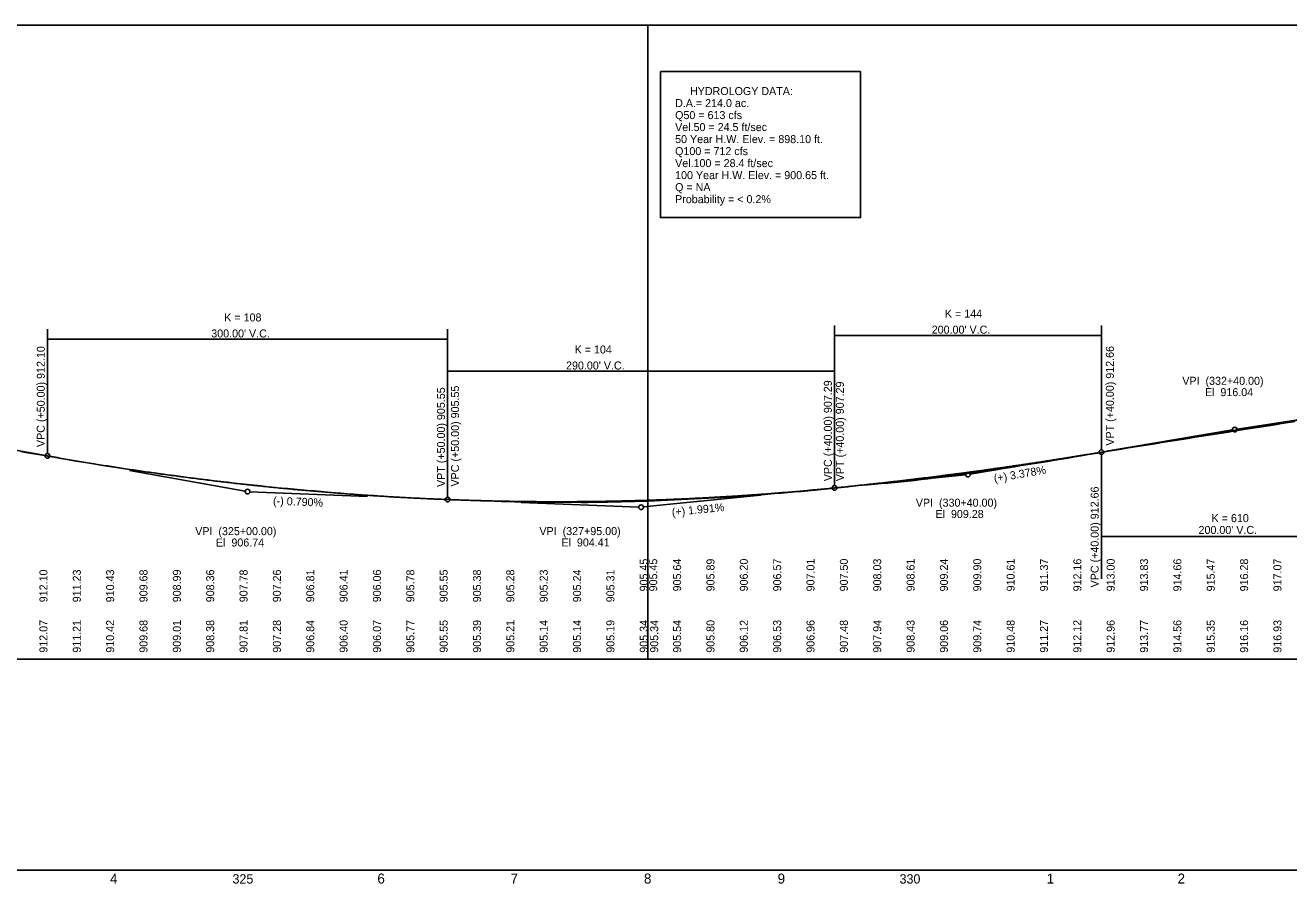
# Model space of a CAD drawing. Extents: x 4180 to 16997695, y 4 to 12629821.
# Drawn here: x 16984753 to 16985700, y 12626778 to 12627421 of the extents above; entities that cross this region are included whole.
import ezdxf

# ---------------------------------------------------------------- set-up
doc = ezdxf.new("R2010")
doc.units = 0
for name, color, linetype in [('Default', 7, 'Continuous'), ('RD_DDB_EX_Tx', 7, 'Continuous'), ('RD_DDB_GradeTX', 7, 'Continuous'), ('RD_DDB_PI', 7, 'Continuous'), ('RD_DDB_Profile_EX', 7, 'Continuous'), ('RD_DDB_Profile_PR', 7, 'Continuous'), ('RD_DDB_StaTX', 7, 'Continuous'), ('RD_DDB_StripGrade', 7, 'Continuous'), ('RD_DDB_StripGrade_PR', 7, 'Continuous'), ('RD_DDB_VCLbl', 7, 'Continuous'), ('RD_GPK_Profile_Cell', 7, 'Continuous')]:
    doc.layers.add(name, color=color, linetype=linetype)

msp = doc.modelspace()

# ---------------------------------------------------------------- linework, layer by layer
at = {"layer": 'Default'}
for points in [[(16983719.88, 12626945.95), (16985219.88, 12626945.95), (16985219.88, 12627420.95), (16983719.88, 12627420.95)], [(16985219.88, 12626945.95), (16986719.88, 12626945.95), (16986719.88, 12627420.95), (16985219.88, 12627420.95)]]:
    msp.add_lwpolyline(points, close=True, dxfattribs=at)
at = {"layer": 'RD_DDB_EX_Tx'}
msp.add_lwpolyline([(16985229.36, 12627386.27), (16985379.36, 12627386.27), (16985379.36, 12627276.8), (16985229.36, 12627276.8)], close=True, dxfattribs=at)
at = {"layer": 'RD_DDB_PI'}
for p, q in [((16985748.85, 12627131.56), (16985661.6, 12627118.25)), ((16985571.13, 12627103), (16985658.15, 12627117.7)), ((16985548.62, 12627099.2), (16985461.6, 12627084.5)), ((16984831.28, 12627087.3), (16984918.15, 12627071.78)), ((16985370.32, 12627075.3), (16985458.13, 12627084.04)), ((16985009.8, 12627067.92), (16984921.62, 12627071.41)), ((16985304.43, 12627068.74), (16985216.62, 12627060)), ((16985124.95, 12627063.38), (16985213.13, 12627059.89))]:
    msp.add_line(p, q, dxfattribs=at)
for centre in [(16985659.88, 12627117.99), (16985459.88, 12627084.21), (16984919.88, 12627071.48), (16985214.88, 12627059.82)]:
    msp.add_circle(centre, 1.75, dxfattribs=at)
at = {"layer": 'RD_DDB_Profile_EX'}
for points in [[(16985619.88, 12627110.57), (16985624.88, 12627111.37), (16985629.88, 12627112.18), (16985634.88, 12627112.98), (16985639.88, 12627113.75), (16985644.88, 12627114.52), (16985649.88, 12627115.3), (16985654.88, 12627116.15), (16985659.88, 12627116.99), (16985664.88, 12627117.83), (16985669.88, 12627118.61), (16985674.88, 12627119.33), (16985679.88, 12627120.05), (16985684.88, 12627120.81), (16985689.88, 12627121.62), (16985694.88, 12627122.43), (16985699.88, 12627123.24), (16985704.88, 12627124.04)], [(16984749.88, 12627101.54), (16984754.88, 12627100.66), (16984759.88, 12627099.81), (16984764.88, 12627098.96), (16984769.88, 12627098.12), (16984774.88, 12627097.24), (16984779.88, 12627096.35), (16984784.88, 12627095.47), (16984789.88, 12627094.63), (16984794.88, 12627093.85), (16984799.88, 12627093.05), (16984804.88, 12627092.24), (16984809.88, 12627091.44), (16984814.88, 12627090.64), (16984819.88, 12627089.89), (16984824.88, 12627089.14), (16984829.88, 12627088.4), (16984834.88, 12627087.66), (16984839.88, 12627086.93), (16984844.88, 12627086.2), (16984849.88, 12627085.48), (16984854.88, 12627084.79), (16984859.88, 12627084.14), (16984864.88, 12627083.49), (16984869.88, 12627082.84), (16984874.88, 12627082.19), (16984879.88, 12627081.54), (16984884.88, 12627080.89), (16984889.88, 12627080.25), (16984894.88, 12627079.67), (16984899.88, 12627079.08), (16984904.88, 12627078.49), (16984909.88, 12627077.91), (16984914.88, 12627077.36), (16984919.88, 12627076.82), (16984924.88, 12627076.28), (16984929.88, 12627075.74), (16984934.88, 12627075.2), (16984939.88, 12627074.65), (16984944.88, 12627074.18), (16984949.88, 12627073.76), (16984954.88, 12627073.33), (16984959.88, 12627072.91), (16984964.88, 12627072.45), (16984969.88, 12627072), (16984974.88, 12627071.55), (16984979.88, 12627071.04), (16984984.88, 12627070.63), (16984989.88, 12627070.22), (16984994.88, 12627069.81), (16984999.88, 12627069.45), (16985004.88, 12627069.13), (16985009.88, 12627068.8), (16985014.88, 12627068.48), (16985019.88, 12627068.12), (16985024.88, 12627067.76), (16985029.88, 12627067.44), (16985034.88, 12627067.16), (16985039.88, 12627066.9), (16985044.88, 12627066.65), (16985049.88, 12627066.41), (16985054.88, 12627066.16), (16985059.88, 12627065.92), (16985064.88, 12627065.74), (16985069.88, 12627065.56), (16985074.88, 12627065.38), (16985079.88, 12627065.2), (16985084.88, 12627065.05), (16985089.88, 12627064.9), (16985094.88, 12627064.74), (16985099.88, 12627064.55), (16985104.88, 12627064.36), (16985109.88, 12627064.19), (16985114.88, 12627064.03), (16985119.88, 12627063.86)], [(16985119.88, 12627063.86), (16985124.88, 12627063.71), (16985129.88, 12627063.65), (16985134.88, 12627063.59), (16985139.88, 12627063.54), (16985144.88, 12627063.48), (16985149.88, 12627063.47), (16985154.88, 12627063.49), (16985159.88, 12627063.5), (16985164.88, 12627063.53), (16985169.88, 12627063.47), (16985174.88, 12627063.45), (16985179.88, 12627063.52), (16985184.88, 12627063.58), (16985189.88, 12627063.65), (16985194.88, 12627063.75), (16985199.88, 12627063.88), (16985204.88, 12627064.01), (16985209.88, 12627064.14), (16985214.88, 12627064.29), (16985219.88, 12627064.47), (16985224.88, 12627064.64), (16985229.88, 12627064.82), (16985234.88, 12627065.04), (16985239.88, 12627065.27), (16985244.88, 12627065.51), (16985249.88, 12627065.75), (16985254.88, 12627065.99), (16985259.88, 12627066.25), (16985264.88, 12627066.51), (16985269.88, 12627066.77), (16985274.88, 12627067.04), (16985279.88, 12627067.37), (16985284.88, 12627067.7), (16985289.88, 12627068.04), (16985294.88, 12627068.38), (16985299.88, 12627068.79), (16985304.88, 12627069.21), (16985309.88, 12627069.63), (16985314.88, 12627070.04), (16985319.88, 12627070.46), (16985324.88, 12627070.87), (16985329.88, 12627071.29), (16985334.88, 12627071.71), (16985339.88, 12627072.13), (16985344.88, 12627072.57), (16985349.88, 12627073.08), (16985354.88, 12627073.59), (16985359.88, 12627074.11), (16985364.88, 12627074.65), (16985369.88, 12627075.19), (16985374.88, 12627075.73), (16985379.88, 12627076.26), (16985384.88, 12627076.67), (16985389.88, 12627077.08), (16985394.88, 12627077.48), (16985399.88, 12627077.94), (16985404.88, 12627078.38), (16985409.88, 12627078.83), (16985414.88, 12627079.35), (16985419.88, 12627079.95), (16985424.88, 12627080.55), (16985429.88, 12627081.17), (16985434.88, 12627081.8), (16985439.88, 12627082.44), (16985444.88, 12627083.09), (16985449.88, 12627083.75), (16985454.88, 12627084.42), (16985459.88, 12627085.08), (16985464.88, 12627085.77), (16985469.88, 12627086.47), (16985474.88, 12627087.17), (16985479.88, 12627087.88), (16985484.88, 12627088.6), (16985489.88, 12627089.38), (16985494.88, 12627090.16), (16985499.88, 12627090.95), (16985504.88, 12627091.75), (16985509.88, 12627092.55), (16985514.88, 12627093.34), (16985519.88, 12627094.16), (16985524.88, 12627095), (16985529.88, 12627095.84), (16985534.88, 12627096.68), (16985539.88, 12627097.53), (16985544.88, 12627098.38), (16985549.88, 12627099.24), (16985554.88, 12627100.08), (16985559.88, 12627100.93), (16985564.88, 12627101.77), (16985569.88, 12627102.58), (16985574.88, 12627103.39), (16985579.88, 12627104.2), (16985584.88, 12627105.01), (16985589.88, 12627105.82), (16985594.88, 12627106.62), (16985599.88, 12627107.41), (16985604.88, 12627108.2), (16985609.88, 12627108.98), (16985614.88, 12627109.77), (16985619.88, 12627110.57)]]:
    msp.add_lwpolyline(points, dxfattribs=at)
at = {"layer": 'RD_DDB_Profile_PR'}
msp.add_line((16984619.88, 12627125.07), (16984769.88, 12627098.27), dxfattribs=at)
for points in [[(16985559.88, 12627101.1), (16985563.88, 12627101.77), (16985567.88, 12627102.45), (16985571.88, 12627103.12), (16985575.88, 12627103.79), (16985579.88, 12627104.46), (16985583.88, 12627105.13), (16985587.88, 12627105.8), (16985591.88, 12627106.46), (16985595.88, 12627107.13), (16985599.88, 12627107.79), (16985603.88, 12627108.45), (16985607.88, 12627109.11), (16985611.88, 12627109.77), (16985615.88, 12627110.43), (16985619.88, 12627111.09), (16985623.88, 12627111.74), (16985627.88, 12627112.4), (16985631.88, 12627113.05), (16985635.88, 12627113.7), (16985639.88, 12627114.35), (16985643.88, 12627115), (16985647.88, 12627115.65), (16985651.88, 12627116.29), (16985655.88, 12627116.94), (16985659.88, 12627117.58), (16985663.88, 12627118.22), (16985667.88, 12627118.86), (16985671.88, 12627119.5), (16985675.88, 12627120.14), (16985679.88, 12627120.78), (16985683.88, 12627121.41), (16985687.88, 12627122.05), (16985691.88, 12627122.68), (16985695.88, 12627123.31), (16985699.88, 12627123.94), (16985703.88, 12627124.57), (16985707.88, 12627125.2), (16985711.88, 12627125.82), (16985715.88, 12627126.45), (16985719.88, 12627127.07), (16985723.88, 12627127.7), (16985727.88, 12627128.32), (16985731.88, 12627128.94), (16985735.88, 12627129.56), (16985739.88, 12627130.17), (16985743.88, 12627130.79), (16985747.88, 12627131.4), (16985751.88, 12627132.02), (16985755.88, 12627132.63), (16985759.88, 12627133.24)], [(16984769.88, 12627098.27), (16984775.88, 12627097.21), (16984781.88, 12627096.16), (16984787.88, 12627095.13), (16984793.88, 12627094.12), (16984799.88, 12627093.12), (16984805.88, 12627092.14), (16984811.88, 12627091.18), (16984817.88, 12627090.23), (16984823.88, 12627089.3), (16984829.88, 12627088.39), (16984835.88, 12627087.49), (16984841.88, 12627086.61), (16984847.88, 12627085.75), (16984853.88, 12627084.9), (16984859.88, 12627084.07), (16984865.88, 12627083.26), (16984871.88, 12627082.46), (16984877.88, 12627081.68), (16984883.88, 12627080.92), (16984889.88, 12627080.17), (16984895.88, 12627079.45), (16984901.88, 12627078.73), (16984907.88, 12627078.04), (16984913.88, 12627077.36), (16984919.88, 12627076.69), (16984925.88, 12627076.05), (16984931.88, 12627075.42), (16984937.88, 12627074.81), (16984943.88, 12627074.21), (16984949.88, 12627073.63), (16984955.88, 12627073.07), (16984961.88, 12627072.52), (16984967.88, 12627071.99), (16984973.88, 12627071.48), (16984979.88, 12627070.98), (16984985.88, 12627070.51), (16984991.88, 12627070.04), (16984997.88, 12627069.6), (16985003.88, 12627069.17), (16985009.88, 12627068.76), (16985015.88, 12627068.36), (16985021.88, 12627067.98), (16985027.88, 12627067.62), (16985033.88, 12627067.27), (16985039.88, 12627066.94), (16985045.88, 12627066.63), (16985051.88, 12627066.34), (16985057.88, 12627066.06), (16985063.88, 12627065.8), (16985069.88, 12627065.55)], [(16985359.88, 12627074.26), (16985363.88, 12627074.66), (16985367.88, 12627075.06), (16985371.88, 12627075.48), (16985375.88, 12627075.89), (16985379.88, 12627076.32), (16985383.88, 12627076.75), (16985387.88, 12627077.18), (16985391.88, 12627077.62), (16985395.88, 12627078.06), (16985399.88, 12627078.52), (16985403.88, 12627078.97), (16985407.88, 12627079.43), (16985411.88, 12627079.9), (16985415.88, 12627080.37), (16985419.88, 12627080.85), (16985423.88, 12627081.34), (16985427.88, 12627081.83), (16985431.88, 12627082.32), (16985435.88, 12627082.82), (16985439.88, 12627083.33), (16985443.88, 12627083.84), (16985447.88, 12627084.36), (16985451.88, 12627084.88), (16985455.88, 12627085.41), (16985459.88, 12627085.94), (16985463.88, 12627086.48), (16985467.88, 12627087.03), (16985471.88, 12627087.58), (16985475.88, 12627088.14), (16985479.88, 12627088.7), (16985483.88, 12627089.27), (16985487.88, 12627089.84), (16985491.88, 12627090.42), (16985495.88, 12627091), (16985499.88, 12627091.59), (16985503.88, 12627092.19), (16985507.88, 12627092.79), (16985511.88, 12627093.39), (16985515.88, 12627094), (16985519.88, 12627094.62), (16985523.88, 12627095.24), (16985527.88, 12627095.87), (16985531.88, 12627096.51), (16985535.88, 12627097.15), (16985539.88, 12627097.79), (16985543.88, 12627098.44), (16985547.88, 12627099.1), (16985551.88, 12627099.76), (16985555.88, 12627100.43), (16985559.88, 12627101.1)], [(16985069.88, 12627065.55), (16985075.68, 12627065.33), (16985081.48, 12627065.13), (16985087.27, 12627064.94), (16985093.08, 12627064.76), (16985098.88, 12627064.61), (16985104.68, 12627064.47), (16985110.48, 12627064.34), (16985116.27, 12627064.23), (16985122.08, 12627064.14), (16985127.88, 12627064.07), (16985133.68, 12627064.01), (16985139.48, 12627063.96), (16985145.27, 12627063.94), (16985151.08, 12627063.92), (16985156.88, 12627063.93), (16985162.68, 12627063.95), (16985168.48, 12627063.99), (16985174.27, 12627064.04), (16985180.08, 12627064.11), (16985185.88, 12627064.19), (16985191.68, 12627064.3), (16985197.48, 12627064.41), (16985203.27, 12627064.55), (16985209.08, 12627064.7), (16985214.88, 12627064.86), (16985220.68, 12627065.05), (16985226.48, 12627065.24), (16985232.27, 12627065.46), (16985238.08, 12627065.69), (16985243.88, 12627065.94), (16985249.68, 12627066.2), (16985255.48, 12627066.48), (16985261.27, 12627066.77), (16985267.08, 12627067.08), (16985272.88, 12627067.41), (16985278.68, 12627067.75), (16985284.48, 12627068.11), (16985290.27, 12627068.49), (16985296.08, 12627068.88), (16985301.88, 12627069.29), (16985307.68, 12627069.71), (16985313.48, 12627070.15), (16985319.27, 12627070.61), (16985325.08, 12627071.08), (16985330.88, 12627071.57), (16985336.68, 12627072.08), (16985342.48, 12627072.6), (16985348.27, 12627073.13), (16985354.08, 12627073.69), (16985359.88, 12627074.26)]]:
    msp.add_spline(points, degree=3, dxfattribs=at)
at = {"layer": 'RD_DDB_VCLbl'}
for p, q in [((16985359.88, 12627196.1), (16985359.88, 12627076.01)), ((16985559.88, 12627196.1), (16985559.88, 12627102.85)), ((16984769.88, 12627193.27), (16984769.88, 12627100.02)), ((16985069.88, 12627193.27), (16985069.88, 12627067.3)), ((16985359.88, 12627188.6), (16985559.88, 12627188.6)), ((16984769.88, 12627185.77), (16985069.88, 12627185.77)), ((16985069.88, 12627169.26), (16985069.88, 12627067.3)), ((16985359.88, 12627169.26), (16985359.88, 12627076.01)), ((16985069.88, 12627161.76), (16985359.88, 12627161.76)), ((16985559.88, 12627006.1), (16985559.88, 12627099.35)), ((16985559.88, 12627037.87), (16985759.88, 12627037.87))]:
    msp.add_line(p, q, dxfattribs=at)
for centre in [(16985559.88, 12627101.1), (16985559.88, 12627101.1), (16984769.88, 12627098.27), (16985359.88, 12627074.26), (16985359.88, 12627074.26), (16985069.88, 12627065.55), (16985069.88, 12627065.55)]:
    msp.add_circle(centre, 1.75, dxfattribs=at)
at = {"layer": 'RD_GPK_Profile_Cell'}
msp.add_line((16972619.88, 12626787.79), (16997196.51, 12626787.79), dxfattribs=at)

# ---------------------------------------------------------------- texts
at = {"layer": 'RD_DDB_EX_Tx'}
for s, p in [('     HYDROLOGY DATA:', (16985240.38, 12627368.65)), ('D.A.= 214.0 ac.', (16985240.38, 12627359.65)), ('Vel.50 = 24.5 ft/sec', (16985240.38, 12627341.65)), ('Q50 = 613 cfs', (16985240.38, 12627350.65)), ('50 Year H.W. Elev. = 898.10 ft.', (16985240.38, 12627332.65)), ('Q100 = 712 cfs', (16985240.38, 12627323.65)), ('Vel.100 = 28.4 ft/sec', (16985240.38, 12627314.65)), ('100 Year H.W. Elev. = 900.65 ft.', (16985240.38, 12627305.65)), ('Q = NA', (16985240.38, 12627296.65)), ('Probability = < 0.2%', (16985240.38, 12627287.65))]:
    msp.add_text(s, height=6, dxfattribs=at).set_placement(p)
at = {"layer": 'RD_DDB_GradeTX'}
for s, rotation, p in [('(+) 3.378%', 9.58636, (16985479.81, 12627078.45)), ('(-) 0.790%', 357.73764, (16984938.91, 12627061.72)), ('(+) 1.991%', 5.68466, (16985238.2, 12627053.1))]:
    msp.add_text(s, height=6, rotation=rotation, dxfattribs=at).set_placement(p)
at = {"layer": 'RD_DDB_PI'}
for s, p in [('VPI  (332+40.00)', (16985620.57, 12627151.53)), ('El  916.04', (16985637.55, 12627143.03)), ('VPI  (330+40.00)', (16985420.81, 12627060.22)), ('El  909.28', (16985435.57, 12627051.72)), ('VPI  (325+00.00)', (16984880.63, 12627038.87)), ('VPI  (327+95.00)', (16985138.67, 12627038.92)), ('El  906.74', (16984896.19, 12627030.37)), ('El  904.41', (16985155.17, 12627030.42))]:
    msp.add_text(s, height=6, dxfattribs=at).set_placement(p)
at = {"layer": 'RD_DDB_StaTX'}
for s, height, p in [('4', 7.5, (16984816.83, 12626777.79)), ('325', 7, (16984908.6, 12626777.79)), ('6', 7.5, (16985017.23, 12626777.79)), ('7', 7.5, (16985117, 12626777.79)), ('8', 7.5, (16985217.03, 12626777.79)), ('9', 7.5, (16985317.23, 12626777.79)), ('330', 7, (16985408.63, 12626777.79)), ('1', 7.5, (16985518.87, 12626777.79)), ('2', 7.5, (16985617.03, 12626777.79))]:
    msp.add_text(s, height=height, dxfattribs=at).set_placement(p)
at = {"layer": 'RD_DDB_StripGrade'}
for s, p in [('912.07', (16984769.88, 12626950.8)), ('911.21', (16984794.88, 12626950.8)), ('910.42', (16984819.88, 12626950.8)), ('909.68', (16984844.88, 12626950.8)), ('909.01', (16984869.88, 12626950.8)), ('908.38', (16984894.88, 12626950.8)), ('907.81', (16984919.88, 12626950.8)), ('907.28', (16984944.88, 12626950.8)), ('906.84', (16984969.88, 12626950.8)), ('906.40', (16984994.88, 12626950.8)), ('906.07', (16985019.88, 12626950.8)), ('905.77', (16985044.88, 12626950.8)), ('905.55', (16985069.88, 12626950.8)), ('905.39', (16985094.88, 12626950.8)), ('905.21', (16985119.88, 12626950.8)), ('905.14', (16985144.88, 12626950.8)), ('905.14', (16985169.88, 12626950.8)), ('905.19', (16985194.88, 12626950.8)), ('905.34', (16985219.88, 12626950.8)), ('905.34', (16985227.71, 12626950.8)), ('905.54', (16985244.88, 12626950.8)), ('905.80', (16985269.88, 12626950.8)), ('906.12', (16985294.88, 12626950.8)), ('906.53', (16985319.88, 12626950.8)), ('906.96', (16985344.88, 12626950.8)), ('907.48', (16985369.88, 12626950.8)), ('907.94', (16985394.88, 12626950.8)), ('908.43', (16985419.88, 12626950.8)), ('909.06', (16985444.88, 12626950.8)), ('909.74', (16985469.88, 12626950.8)), ('910.48', (16985494.88, 12626950.8)), ('911.27', (16985519.88, 12626950.8)), ('912.12', (16985544.88, 12626950.8)), ('912.96', (16985569.88, 12626950.8)), ('913.77', (16985594.88, 12626950.8)), ('914.56', (16985619.88, 12626950.8)), ('915.35', (16985644.88, 12626950.8)), ('916.16', (16985669.88, 12626950.8)), ('916.93', (16985694.88, 12626950.8))]:
    msp.add_text(s, height=6, rotation=90, dxfattribs=at).set_placement(p)
at = {"layer": 'RD_DDB_StripGrade_PR'}
for s, p in [('905.45', (16985219.88, 12626996.74)), ('905.45', (16985226.97, 12626996.74)), ('905.64', (16985244.88, 12626996.74)), ('905.89', (16985269.88, 12626996.74)), ('906.20', (16985294.88, 12626996.74)), ('906.57', (16985319.88, 12626996.74)), ('907.01', (16985344.88, 12626996.74)), ('907.50', (16985369.88, 12626996.74)), ('908.03', (16985394.88, 12626996.74)), ('908.61', (16985419.88, 12626996.74)), ('909.24', (16985444.88, 12626996.74)), ('909.90', (16985469.88, 12626996.74)), ('910.61', (16985494.88, 12626996.74)), ('911.37', (16985519.88, 12626996.74)), ('912.16', (16985544.88, 12626996.74)), ('913.00', (16985569.88, 12626996.74)), ('913.83', (16985594.88, 12626996.74)), ('914.66', (16985619.88, 12626996.74)), ('915.47', (16985644.88, 12626996.74)), ('916.28', (16985669.88, 12626996.74)), ('917.07', (16985694.88, 12626996.74)), ('912.10', (16984769.88, 12626988.58)), ('911.23', (16984794.88, 12626988.58)), ('910.43', (16984819.88, 12626988.58)), ('909.68', (16984844.88, 12626988.58)), ('908.99', (16984869.88, 12626988.58)), ('908.36', (16984894.88, 12626988.58)), ('907.78', (16984919.88, 12626988.58)), ('907.26', (16984944.88, 12626988.58)), ('906.81', (16984969.88, 12626988.58)), ('906.41', (16984994.88, 12626988.58)), ('906.06', (16985019.88, 12626988.58)), ('905.78', (16985044.88, 12626988.58)), ('905.55', (16985069.88, 12626988.58)), ('905.38', (16985094.88, 12626988.58)), ('905.28', (16985119.88, 12626988.58)), ('905.23', (16985144.88, 12626988.58)), ('905.24', (16985169.88, 12626988.58)), ('905.31', (16985194.88, 12626988.58))]:
    msp.add_text(s, height=6, rotation=90, dxfattribs=at).set_placement(p)
at = {"layer": 'RD_DDB_VCLbl'}
for s, p in [('K = 144', (16985442.64, 12627201.85)), ('K = 108', (16984902.43, 12627199.02)), ("300.00' V.C.", (16984892.68, 12627187.02)), ("200.00' V.C.", (16985432.74, 12627189.85)), ('K = 104', (16985165.06, 12627175.01)), ("290.00' V.C.", (16985158.62, 12627163.01)), ('K = 610', (16985642.52, 12627048.63)), ("200.00' V.C.", (16985632.74, 12627039.78))]:
    msp.add_text(s, height=6, dxfattribs=at).set_placement(p)
for s, p in [('VPC (+50.00) 912.10', (16984767.88, 12627104.88)), ('VPT (+40.00) 912.66', (16985569.28, 12627105.93)), ('VPT (+50.00) 905.55', (16985067.88, 12627074.95)), ('VPC (+50.00) 905.55', (16985078.42, 12627075.31)), ('VPC (+40.00) 907.29', (16985357.88, 12627079.3)), ('VPT (+40.00) 907.29', (16985366.88, 12627079.29)), ('VPC (+40.00) 912.66', (16985557.88, 12626999.71))]:
    msp.add_text(s, height=6, rotation=90, dxfattribs=at).set_placement(p)

doc.saveas('drawing.dxf')
